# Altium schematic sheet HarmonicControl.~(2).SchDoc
size A
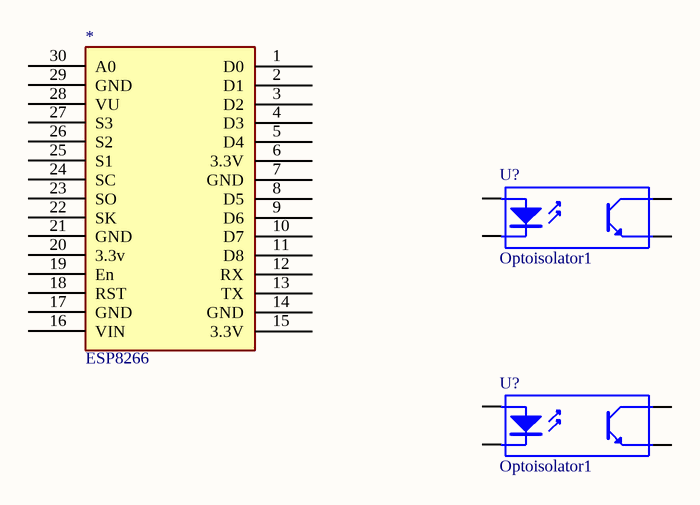
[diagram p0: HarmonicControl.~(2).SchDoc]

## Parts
(Parts that share a designator on the sheet are numbered #1, #2 ... from top to bottom, then left to right.)
*  ESP8266  [Model Name]
U?#1  Optoisolator1  [DIP-4]
U?#2  Optoisolator1  [DIP-4]

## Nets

Not connected (* = marked no-connect by the designer): * 1(D0) 2(D1) 3(D2) 4(D3) 5(D4) 6(3.3V) 7(GND) 8(D5) 9(D6) 10(D7) 11(D8) 12(RX) 13(TX) 14(GND) 15(3.3V) 16(VIN) 17(GND) 18(RST) 19(En) 20(3.3v) 21(GND) 22(SK) 23(SO) 24(SC) 25(S1) 26(S2) 27(S3) 28(VU) 29(GND) 30(A0); U?#1 1(A) 2(K) 3(E) 4(C); U?#2 1(A) 2(K) 3(E) 4(C)

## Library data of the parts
* = ESP8266_Node_MCU_V3
U?#1 U?#2 = Optoisolator1: 4-Pin Phototransistor Optocoupler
